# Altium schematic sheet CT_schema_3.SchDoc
size 298 x 247 mm
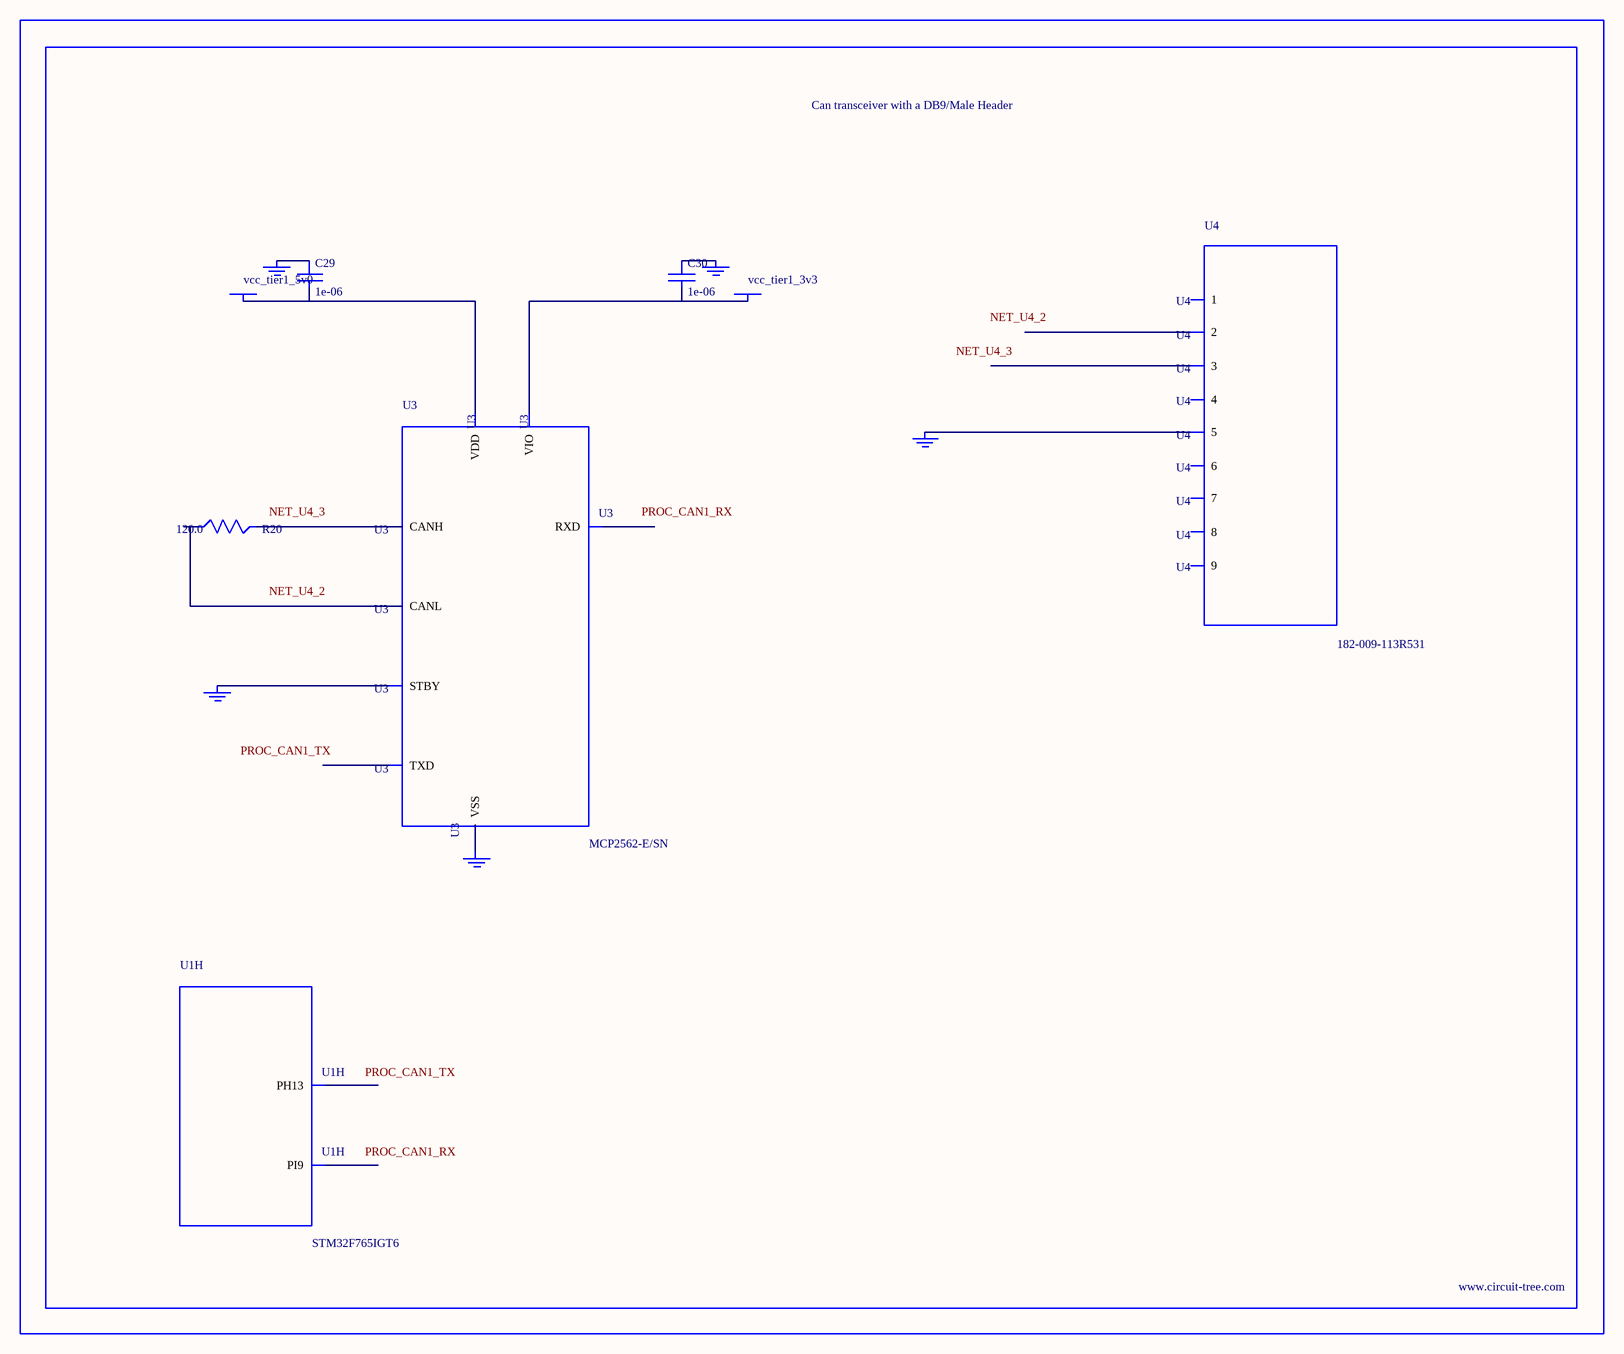
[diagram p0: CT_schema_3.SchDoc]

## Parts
BORDER2  (no value)
C29  1e-06  [C0603]
C30  1e-06  [C0603]
GND_INSTANCE_2_0  (no value)
GND_INSTANCE_2_1  (no value)
GND_INSTANCE_2_2  (no value)
GND_INSTANCE_2_3  (no value)
GND_INSTANCE_2_4  (no value)
POWER_INSTANCE_2_0  vcc_tier1_5v0
POWER_INSTANCE_2_1  vcc_tier1_3v3
R20  120.0  [R0603]
U1  STM32F765IGT6  [LQFP176]  (part H of 14)
U3  MCP2562-E/SN  [SOIC-8]
U4  182-009-113R531  [182-009-MALE]

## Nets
NetC29_1: C29.1 GND_INSTANCE_2_0.0(GND)
NetC29_2: C29.2 POWER_INSTANCE_2_0.0(PWR) U3.3(VDD)
NetC30_1: C30.1 GND_INSTANCE_2_1.0(GND)
NetC30_2: C30.2 POWER_INSTANCE_2_1.0(PWR) U3.5(VIO)
NetGND_INSTANCE_2_2_0: GND_INSTANCE_2_2.0(GND) U3.8(STBY)
NetGND_INSTANCE_2_3_0: GND_INSTANCE_2_3.0(GND) U3.2(VSS)
NetGND_INSTANCE_2_4_0: GND_INSTANCE_2_4.0(GND) U4.5
NetR20_1: R20.1 U3.6(CANL)
NetR20_2: R20.2 U3.7(CANH)

Not connected (* = marked no-connect by the designer): U1 11(PI9) 128(PH13); U3 1(TXD) 4(RXD); U4 1 2 3 4 6 7 8 9

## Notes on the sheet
- Labels drawn without touching a wire or pin: NET_U4_2, NET_U4_3, PROC_CAN1_RX, PROC_CAN1_TX

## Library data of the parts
BORDER2 = BORDER_PAGE2
C29 C30 = C0603C105K3RACTU
GND_INSTANCE_2_0-GND_INSTANCE_2_4 = GND
POWER_INSTANCE_2_0 POWER_INSTANCE_2_1 = PWR
R20 = RC0603JR-07120RL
